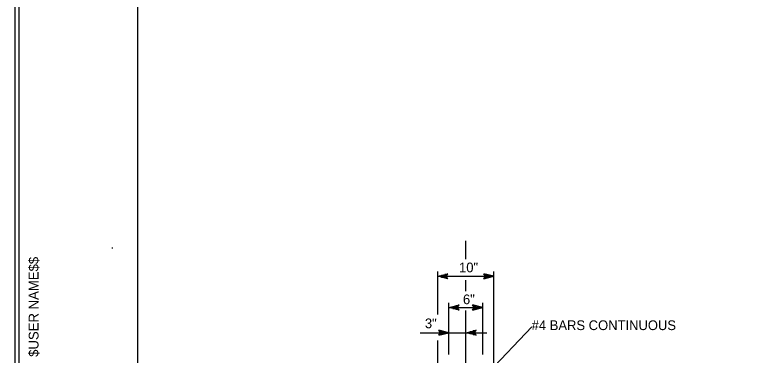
# Model space of a CAD drawing. Extents: x 504255 to 505955, y 659986 to 661086.
# Drawn here: x 504255.5 to 504692.9, y 660335.6 to 660536.4 of the extents above; entities that cross this region are included whole.
import ezdxf

# ---------------------------------------------------------------- set-up
doc = ezdxf.new("R2010")
doc.units = 0
doc.layers.add('Level 62', color=7, linetype='Continuous')
doc.layers.add('Level1', color=7, linetype='Continuous')

msp = doc.modelspace()

# ---------------------------------------------------------------- linework, layer by layer
at = {"layer": 'Level 62'}
msp.add_lwpolyline([(505955.48, 661086.39), (504255.48, 661086.39), (504255.48, 659986.39), (505955.48, 659986.39)], close=True, dxfattribs=at)
at = {"layer": 'Level1'}
for p, q in [((504521.94, 660392.21), (504521.94, 660403.03)), ((504313.37, 660398.7), (504312.84, 660398.7)), ((504505.32, 660359.59), (504505.32, 660384.89)), ((504538.57, 660271.15), (504538.57, 660384.89)), ((504505.32, 660382.13), (504538.57, 660382.13)), ((504521.94, 660373.34), (504521.94, 660379.83)), ((504511.96, 660335.92), (504511.96, 660366.44)), ((504531.92, 660335.92), (504531.92, 660366.44)), ((504511.96, 660363.67), (504531.92, 660363.67)), ((504521.94, 660321.46), (504521.94, 660361.89)), ((504494.92, 660348.83), (504534.41, 660348.83)), ((504523.41, 660312.86), (504561, 660352.36)), ((504505.32, 660271.15), (504505.32, 660344.19))]:
    msp.add_line(p, q, dxfattribs=at)
for points in [[(504257.9, 660010.3), (505953.07, 660010.3), (505953.07, 661062.47), (504257.9, 661062.47), (504257.9, 660010.3)], [(504327.92, 660023.67), (505946.29, 660023.67), (505946.29, 661038.56), (504327.92, 661038.56), (504327.92, 660023.67)], [(504511.36, 660380.64), (504505.32, 660382.13), (504511.36, 660383.63), (504510.65, 660383.13), (504509.61, 660383.13), (504510.61, 660382.64), (504507.59, 660382.64), (504510.27, 660382.13), (504507.59, 660381.63), (504510.61, 660381.63), (504509.61, 660381.14), (504510.65, 660381.14), (504511.36, 660380.64), (504510.35, 660382.13), (504511.36, 660383.63)], [(504532.52, 660380.64), (504538.57, 660382.13), (504532.52, 660383.63), (504533.24, 660383.13), (504534.27, 660383.13), (504533.27, 660382.64), (504536.29, 660382.64), (504533.61, 660382.13), (504536.29, 660381.63), (504533.27, 660381.63), (504534.27, 660381.14), (504533.24, 660381.14), (504532.52, 660380.64), (504533.53, 660382.13), (504532.52, 660383.63)], [(504518.01, 660362.18), (504511.96, 660363.67), (504518.01, 660365.18), (504517.3, 660364.68), (504516.26, 660364.68), (504517.26, 660364.18), (504514.24, 660364.18), (504516.93, 660363.67), (504514.24, 660363.18), (504517.26, 660363.18), (504516.26, 660362.68), (504517.3, 660362.68), (504518.01, 660362.18), (504517, 660363.67), (504518.01, 660365.18)], [(504525.87, 660362.18), (504531.92, 660363.67), (504525.87, 660365.18), (504526.58, 660364.68), (504527.62, 660364.68), (504526.62, 660364.18), (504529.64, 660364.18), (504526.95, 660363.67), (504529.64, 660363.18), (504526.62, 660363.18), (504527.62, 660362.68), (504526.58, 660362.68), (504525.87, 660362.18), (504526.88, 660363.67), (504525.87, 660365.18)], [(504505.93, 660347.34), (504511.96, 660348.83), (504505.93, 660350.33), (504506.64, 660349.84), (504507.67, 660349.84), (504506.67, 660349.34), (504509.69, 660349.34), (504507.01, 660348.83), (504509.69, 660348.34), (504506.67, 660348.34), (504507.67, 660347.84), (504506.64, 660347.84), (504505.93, 660347.34), (504506.93, 660348.83), (504505.93, 660350.33)], [(504527.98, 660347.34), (504521.94, 660348.83), (504527.98, 660350.33), (504527.27, 660349.84), (504526.24, 660349.84), (504527.24, 660349.34), (504524.22, 660349.34), (504526.9, 660348.83), (504524.22, 660348.34), (504527.24, 660348.34), (504526.24, 660347.84), (504527.27, 660347.84), (504527.98, 660347.34), (504526.97, 660348.83), (504527.98, 660350.33)]]:
    msp.add_lwpolyline(points, dxfattribs=at)

# ---------------------------------------------------------------- texts
msp.add_text('$USER NAME$$', height=5.797, rotation=90, dxfattribs=at).set_placement((504269.49, 660334.57))
for s, height, p in [('10"', 5.739, (504517.94, 660384.46)), ('6"', 5.739, (504520.25, 660365.63)), ('3"', 5.739, (504497.78, 660351.46)), ('#4 BARS CONTINUOUS', 5.7392, (504560.83, 660350.36))]:
    msp.add_text(s, height=height, dxfattribs=at).set_placement(p)

doc.saveas('drawing.dxf')
